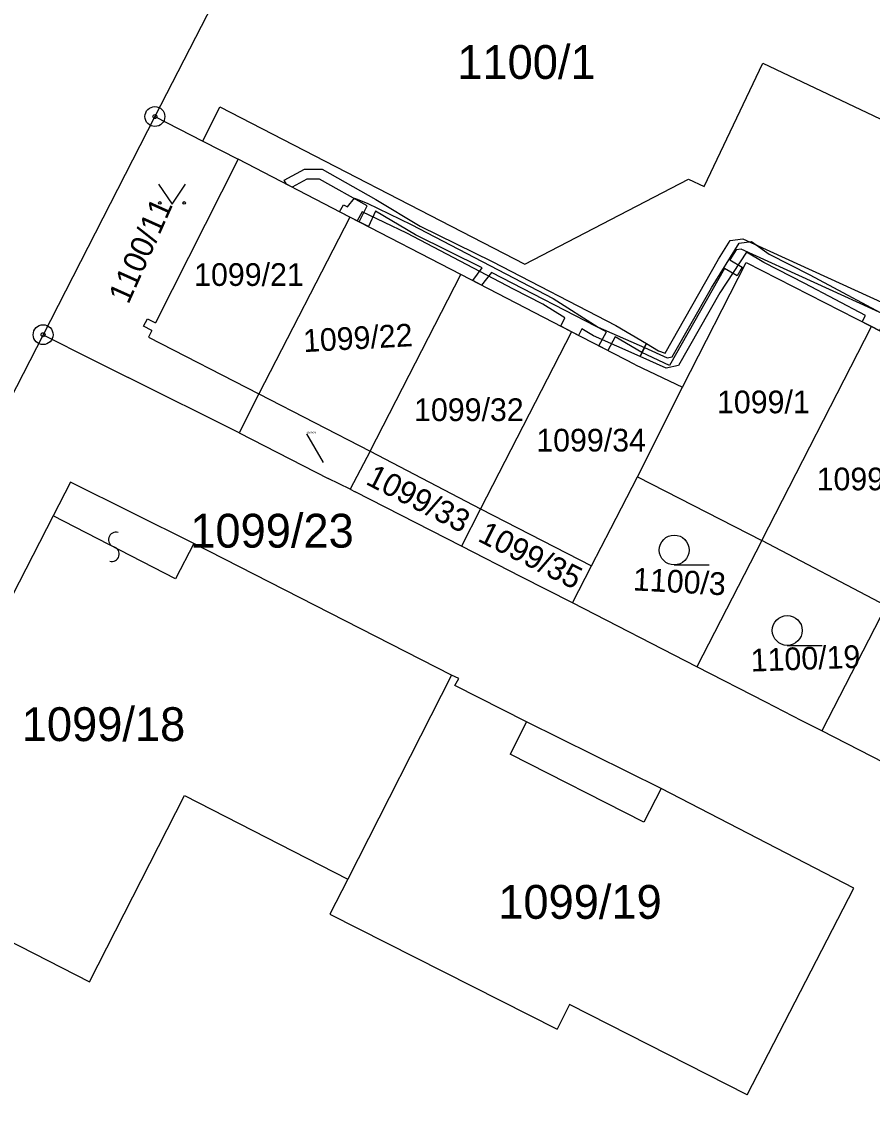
# Model space of a CAD drawing. Extents: x -621172 to -616925, y -1123899 to -1119548.
# Drawn here: x -619066 to -619023.2, y -1121541.1 to -1121486.6 of the extents above; entities that cross this region are included whole.
import ezdxf

# ---------------------------------------------------------------- set-up
doc = ezdxf.new("R2010")
doc.units = 0
for name, color, linetype in [('Vrstva 1', 7, 'Continuous'), ('Vrstva 16', 7, 'Continuous'), ('Vrstva 18', 7, 'Continuous'), ('Vrstva 19', 7, 'Continuous'), ('Vrstva 24', 7, 'Continuous'), ('Vrstva 25', 7, 'Continuous'), ('Vrstva 4', 7, 'Continuous')]:
    doc.layers.add(name, color=color, linetype=linetype)

msp = doc.modelspace()

# ---------------------------------------------------------------- linework, layer by layer
at = {"layer": 'Vrstva 1'}
for points in [[(-619056.09, -1121485.11), (-619059.29, -1121491.34)], [(-619031.69, -1121494.86), (-619028.74, -1121488.65)], [(-619028.74, -1121488.65), (-619013.7, -1121495.79)], [(-619056.89, -1121492.57), (-619056.03, -1121490.86)], [(-619056.03, -1121490.86), (-619040.7, -1121498.76)], [(-619059.29, -1121491.34), (-619064.91, -1121502.3)], [(-619059.29, -1121491.34), (-619056.89, -1121492.57)], [(-619056.89, -1121492.57), (-619055.11, -1121493.48)], [(-619055.11, -1121493.48), (-619059.26, -1121501.71)], [(-619049.49, -1121496.39), (-619055.11, -1121493.48)], [(-619052.79, -1121494.53), (-619051.78, -1121493.98)], [(-619051.78, -1121493.98), (-619050.88, -1121493.98)], [(-619050.88, -1121493.98), (-619048.18, -1121495.51)], [(-619052.68, -1121494.74), (-619052.79, -1121494.53)], [(-619052.4, -1121494.89), (-619052.68, -1121494.74)], [(-619051.66, -1121494.48), (-619052.4, -1121494.89)], [(-619051.02, -1121494.48), (-619051.66, -1121494.48)], [(-619048.63, -1121495.83), (-619051.02, -1121494.48)], [(-619040.7, -1121498.76), (-619032.48, -1121494.48)], [(-619032.48, -1121494.48), (-619031.69, -1121494.86)], [(-619050.01, -1121496.12), (-619049.82, -1121495.77), (-619049.61, -1121495.88), (-619049.26, -1121495.44), (-619048.63, -1121495.69), (-619046.41, -1121496.76), (-619039.27, -1121500.49), (-619037.01, -1121501.92), (-619034.69, -1121502.95)], [(-619049.02, -1121496.63), (-619048.63, -1121495.83)], [(-619048.18, -1121495.51), (-619045.96, -1121496.85)], [(-619049.49, -1121496.39), (-619054.06, -1121505.28)], [(-619034.91, -1121503.39), (-619037.25, -1121502.36), (-619037.83, -1121502), (-619038, -1121502.34), (-619038.89, -1121501.88), (-619038.68, -1121501.46), (-619039.8, -1121500.77), (-619041.27, -1121500.01), (-619046.63, -1121497.2), (-619048.88, -1121496.13), (-619049.12, -1121496.58), (-619049.49, -1121496.39), (-619050.01, -1121496.12)], [(-619043.92, -1121499.27), (-619049.49, -1121496.39)], [(-619048.2, -1121496.09), (-619048.56, -1121496.87)], [(-619046.2, -1121497.29), (-619048.2, -1121496.09)], [(-619048.56, -1121496.87), (-619049.02, -1121496.63)], [(-619045.96, -1121496.85), (-619042.34, -1121498.63)], [(-619042.84, -1121498.94), (-619046.2, -1121497.29)], [(-619017.5, -1121503.65), (-619017.72, -1121504.09), (-619020.32, -1121502.7), (-619022.04, -1121501.59), (-619022.44, -1121502.34), (-619022.88, -1121502.1), (-619022.48, -1121501.35), (-619029.82, -1121498), (-619030.08, -1121498.03), (-619030.4, -1121498.54), (-619029.78, -1121498.9), (-619030.02, -1121499.34), (-619030.66, -1121498.97), (-619033.43, -1121503.85), (-619034.82, -1121503.2), (-619034.59, -1121502.75), (-619033.98, -1121503.11), (-619033.65, -1121503.23), (-619030.96, -1121498.5), (-619030.38, -1121497.57), (-619029.74, -1121497.48), (-619022.01, -1121501.01), (-619020.06, -1121502.26), (-619017.5, -1121503.65)], [(-619034.69, -1121502.95), (-619033.54, -1121503.47), (-619033.29, -1121503.41), (-619031.32, -1121499.94), (-619029.92, -1121497.7), (-619029.31, -1121497.61), (-619028.42, -1121498.25), (-619026.38, -1121499.29), (-619021.87, -1121501.7), (-619019.25, -1121502.91), (-619018.96, -1121502.39)], [(-619042.34, -1121498.63), (-619036.13, -1121501.84)], [(-619018.51, -1121502.61), (-619018.81, -1121503.14), (-619017.6, -1121503.85), (-619017.82, -1121504.3), (-619019.27, -1121503.45), (-619022.09, -1121502.14), (-619022.7, -1121501.8), (-619022.85, -1121502.11), (-619023.27, -1121501.89), (-619023.74, -1121501.65), (-619023.58, -1121501.33), (-619026.62, -1121499.73), (-619028.68, -1121498.67), (-619029.56, -1121498.15), (-619030.9, -1121500.2), (-619032.97, -1121503.85), (-619033.6, -1121503.99), (-619034.91, -1121503.39)], [(-619043.32, -1121499.58), (-619042.84, -1121498.94)], [(-619042.38, -1121499.17), (-619042.88, -1121499.81)], [(-619036.59, -1121502.16), (-619042.38, -1121499.17)], [(-619032.78, -1121504.94), (-619029.58, -1121498.68)], [(-619029.58, -1121498.68), (-619023.27, -1121501.89)], [(-619048.48, -1121508.15), (-619043.92, -1121499.27)], [(-619038.36, -1121502.15), (-619043.92, -1121499.27)], [(-619042.88, -1121499.81), (-619043.32, -1121499.58)], [(-619059.86, -1121501.88), (-619059.66, -1121501.5)], [(-619059.45, -1121502.09), (-619059.86, -1121501.88)], [(-619059.66, -1121501.5), (-619059.26, -1121501.71)], [(-619036.13, -1121501.84), (-619034.59, -1121502.75)], [(-619028.79, -1121512.64), (-619023.27, -1121501.89)], [(-619023.27, -1121501.89), (-619018, -1121504.65)], [(-619064.91, -1121502.3), (-619094.57, -1121560.13)], [(-619064.91, -1121502.3), (-619062.45, -1121503.54)], [(-619059.45, -1121502.09), (-619059.62, -1121502.43)], [(-619059.62, -1121502.43), (-619054.06, -1121505.28)], [(-619038.36, -1121502.15), (-619042.93, -1121511.05)], [(-619035.13, -1121503.82), (-619038.36, -1121502.15)], [(-619036.98, -1121502.86), (-619036.59, -1121502.16)], [(-619036.16, -1121502.41), (-619036.53, -1121503.09)], [(-619034.82, -1121503.2), (-619036.16, -1121502.41)], [(-619036.53, -1121503.09), (-619036.98, -1121502.86)], [(-619034.69, -1121502.95), (-619034.91, -1121503.39)], [(-619034.91, -1121503.39), (-619034.69, -1121502.95)], [(-619034.59, -1121502.75), (-619034.82, -1121503.2)], [(-619062.45, -1121503.54), (-619060.64, -1121504.46)], [(-619035.13, -1121503.82), (-619032.78, -1121504.94)], [(-619055.06, -1121507.23), (-619060.64, -1121504.46)], [(-619035.03, -1121509.44), (-619032.78, -1121504.94)], [(-619054.06, -1121505.28), (-619055.06, -1121507.23)], [(-619054.06, -1121505.28), (-619048.48, -1121508.15)], [(-619055.06, -1121507.23), (-619050.58, -1121509.52)], [(-619048.48, -1121508.15), (-619049.47, -1121510.07)], [(-619048.48, -1121508.15), (-619042.93, -1121511.05)], [(-619049.47, -1121510.07), (-619050.58, -1121509.52)], [(-619036.37, -1121512.04), (-619035.03, -1121509.44)], [(-619035.03, -1121509.44), (-619028.79, -1121512.64)], [(-619063.54, -1121509.71), (-619064.4, -1121511.4)], [(-619057.33, -1121512.79), (-619063.54, -1121509.71)], [(-619049.47, -1121510.07), (-619049.23, -1121510.19)], [(-619043.89, -1121512.92), (-619049.23, -1121510.19)], [(-619042.93, -1121511.05), (-619043.89, -1121512.92)], [(-619042.93, -1121511.05), (-619037.34, -1121513.92)], [(-619064.4, -1121511.4), (-619068.52, -1121519.41)], [(-619037.34, -1121513.92), (-619036.37, -1121512.04)], [(-619044.38, -1121519.4), (-619057.33, -1121512.79)], [(-619028.79, -1121512.64), (-619032.05, -1121518.99)], [(-619022.54, -1121515.92), (-619028.79, -1121512.64)], [(-619040.89, -1121514.46), (-619043.89, -1121512.92)], [(-619038.3, -1121515.78), (-619037.34, -1121513.92)], [(-619038.3, -1121515.78), (-619040.89, -1121514.46)], [(-619032.05, -1121518.99), (-619038.3, -1121515.78)], [(-619022.54, -1121515.92), (-619025.77, -1121522.21)], [(-619028.59, -1121520.76), (-619032.05, -1121518.99)], [(-619044.38, -1121519.4), (-619049.6, -1121529.65)], [(-619044.02, -1121519.58), (-619044.38, -1121519.4)], [(-619044.21, -1121519.92), (-619044.02, -1121519.58)], [(-619040.61, -1121521.76), (-619044.21, -1121519.92)], [(-619026.77, -1121521.7), (-619028.59, -1121520.76)], [(-619033.85, -1121525.1), (-619040.61, -1121521.76)], [(-619025.77, -1121522.21), (-619026.77, -1121521.7)], [(-619019.48, -1121525.43), (-619025.77, -1121522.21)], [(-619024.16, -1121530.11), (-619033.85, -1121525.1)], [(-619062.57, -1121534.81), (-619057.8, -1121525.46)], [(-619057.8, -1121525.46), (-619049.6, -1121529.65)], [(-619073.1, -1121529.44), (-619062.57, -1121534.81)], [(-619049.6, -1121529.65), (-619050.5, -1121531.41)], [(-619029.53, -1121540.5), (-619024.16, -1121530.11)], [(-619050.5, -1121531.41), (-619039.08, -1121537.19)], [(-619038.45, -1121535.95), (-619039.08, -1121537.19)], [(-619029.53, -1121540.5), (-619038.45, -1121535.95)]]:
    msp.add_lwpolyline(points, dxfattribs=at)
at = {"layer": 'Vrstva 16'}
msp.add_line((-619051.68, -1121507.28), (-619050.832, -1121508.717), dxfattribs=at)
at = {"layer": 'Vrstva 24'}
for centre, radius in [((-619059.29, -1121491.34), 0.5), ((-619059.29, -1121491.34), 0.1), ((-619064.91, -1121502.3), 0.5), ((-619064.91, -1121502.3), 0.1)]:
    msp.add_circle(centre, radius, dxfattribs=at)
at = {"layer": 'Vrstva 25'}
for p, q in [((-619033.19, -1121513.87), (-619031.44, -1121513.87)), ((-619027.51, -1121517.91), (-619025.76, -1121517.91))]:
    msp.add_line(p, q, dxfattribs=at)
msp.add_lwpolyline([(-619059.11, -1121494.73), (-619058.43, -1121495.75), (-619057.75, -1121494.73)], dxfattribs=at)
for centre, radius in [((-619059.042, -1121495.682), 0.068), ((-619057.819, -1121495.682), 0.068), ((-619033.19, -1121513.12), 0.75), ((-619027.51, -1121517.16), 0.75)]:
    msp.add_circle(centre, radius, dxfattribs=at)
for centre, start, end in [((-619061.244, -1121512.6), 73.6196, 253.6196), ((-619061.456, -1121513.32), 253.6196, 73.6196)]:
    msp.add_arc(centre, 0.375, start, end, dxfattribs=at)
at = {"layer": 'Vrstva 4'}
for points in [[(-619058.25, -1121514.57), (-619064.4, -1121511.4)], [(-619057.33, -1121512.79), (-619058.25, -1121514.57)], [(-619040.61, -1121521.76), (-619041.43, -1121523.38)], [(-619034.71, -1121526.79), (-619041.43, -1121523.38)], [(-619033.85, -1121525.1), (-619034.71, -1121526.79)]]:
    msp.add_lwpolyline(points, dxfattribs=at)

# ---------------------------------------------------------------- texts
at = {"layer": 'Vrstva 16'}
msp.add_text('1099/23', height=1.7, dxfattribs=at).set_placement((-619057.514, -1121513))
at = {"layer": 'Vrstva 18'}
for s, height, p in [('1100/1', 1.7, (-619044.093, -1121489.45)), ('1099/23', 0.1, (-619051.68, -1121507.28))]:
    msp.add_text(s, height=height, dxfattribs=at).set_placement(p)
for s, rotation, p in [('1100/11', 65.8677, (-619060.625, -1121500.814)), ('1099/33', 332.9627, (-619048.754, -1121509.783)), ('1099/35', 333.2057, (-619043.118, -1121512.644)), ('1100/3', 356.8736, (-619035.286, -1121515.145)), ('1100/19', 2.0453, (-619029.326, -1121519.23))]:
    msp.add_text(s, height=1.14, rotation=rotation, dxfattribs=at).set_placement(p)
at = {"layer": 'Vrstva 19'}
for s, height, p in [('1099/21', 1.14, (-619057.32, -1121499.85)), ('1099/1', 1.14, (-619031.041, -1121506.25)), ('1099/32', 1.14, (-619046.266, -1121506.64)), ('1099/34', 1.14, (-619040.123, -1121508.17)), ('1099/36', 1.14, (-619026.033, -1121510.12)), ('1099/18', 1.7, (-619065.983, -1121522.72)), ('1099/19', 1.7, (-619042.035, -1121531.65))]:
    msp.add_text(s, height=height, dxfattribs=at).set_placement(p)
msp.add_text('1099/22', height=1.14, rotation=3.1798, dxfattribs=at).set_placement((-619051.814, -1121503.181))

doc.saveas('drawing.dxf')
